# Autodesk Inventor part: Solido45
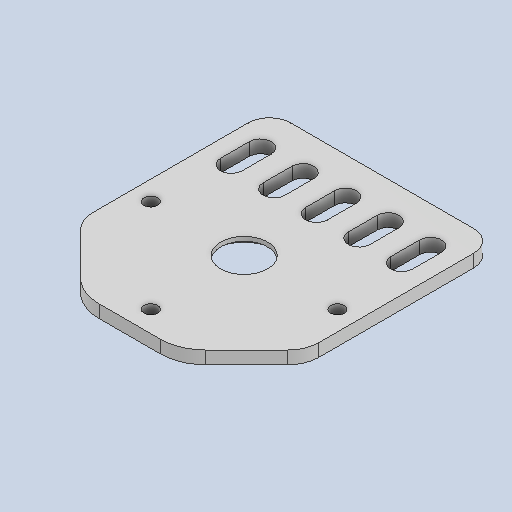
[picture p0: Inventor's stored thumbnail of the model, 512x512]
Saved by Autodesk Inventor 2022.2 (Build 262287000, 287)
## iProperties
Created: 2024-10
Part Number: Solido45
Material: Acciaio
Document SubType Name: Modeling
Designer: 18907419
Density: 7.85 g/cm^3
Appearance: Default
Author: 18907419
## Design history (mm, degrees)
feature "Solido45"
node "Solido1"
